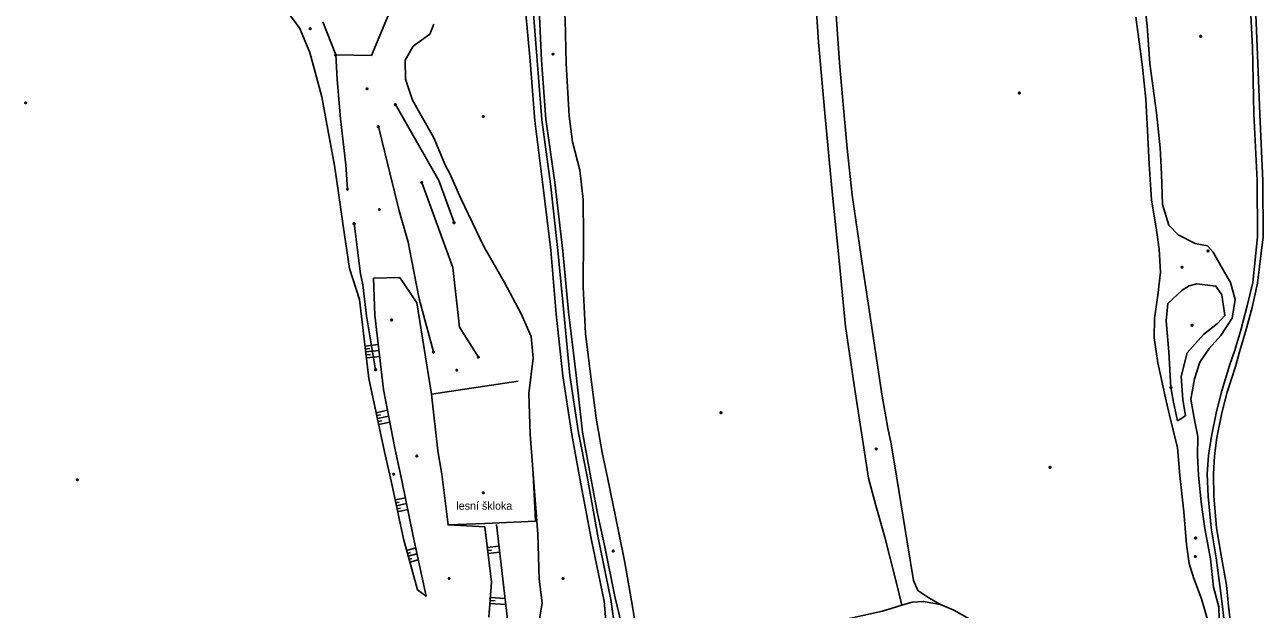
# Model space of a CAD drawing. Extents: x -664960 to -662754, y -993849 to -991145.
# Drawn here: x -663856.5 to -663361.4, y -992059.4 to -991825.9 of the extents above; entities that cross this region are included whole.
import ezdxf

# ---------------------------------------------------------------- set-up
doc = ezdxf.new("R2010")
doc.units = 0
for name, color, linetype in [('Vrstva 13', 7, 'Continuous'), ('Vrstva 18', 7, 'Continuous'), ('Vrstva 27', 7, 'Continuous'), ('Vrstva 28', 7, 'Continuous'), ('Vrstva 33', 7, 'Continuous'), ('Vrstva 63', 7, 'Continuous')]:
    doc.layers.add(name, color=color, linetype=linetype)

msp = doc.modelspace()

# ---------------------------------------------------------------- linework, layer by layer
at = {"layer": 'Vrstva 13'}
for points in [[(-663742.203, -991827.14), (-663742.023, -991827.44), (-663742.203, -991827.74), (-663742.563, -991827.74), (-663742.743, -991827.44), (-663742.563, -991827.14), (-663742.203, -991827.14)], [(-663386.265, -991830.239), (-663386.085, -991830.539), (-663386.265, -991830.839), (-663386.625, -991830.839), (-663386.805, -991830.539), (-663386.625, -991830.239), (-663386.265, -991830.239)], [(-663645.151, -991837.335), (-663644.971, -991837.635), (-663645.151, -991837.935), (-663645.511, -991837.935), (-663645.691, -991837.635), (-663645.511, -991837.335), (-663645.151, -991837.335)], [(-663855.937, -991856.804), (-663855.757, -991857.104), (-663855.937, -991857.404), (-663856.297, -991857.404), (-663856.477, -991857.104), (-663856.297, -991856.804), (-663855.937, -991856.804)], [(-663458.726, -991852.828), (-663458.546, -991853.128), (-663458.726, -991853.428), (-663459.086, -991853.428), (-663459.266, -991853.128), (-663459.086, -991852.828), (-663458.726, -991852.828)], [(-663672.978, -991862.261), (-663672.798, -991862.561), (-663672.978, -991862.861), (-663673.338, -991862.861), (-663673.518, -991862.561), (-663673.338, -991862.261), (-663672.978, -991862.261)], [(-663714.501, -991899.41), (-663714.321, -991899.71), (-663714.501, -991900.01), (-663714.861, -991900.01), (-663715.041, -991899.71), (-663714.861, -991899.41), (-663714.501, -991899.41)], [(-663709.667, -991943.553), (-663709.487, -991943.853), (-663709.667, -991944.153), (-663710.027, -991944.153), (-663710.207, -991943.853), (-663710.027, -991943.553), (-663709.667, -991943.553)], [(-663683.574, -991963.56), (-663683.394, -991963.86), (-663683.574, -991964.16), (-663683.934, -991964.16), (-663684.114, -991963.86), (-663683.934, -991963.56), (-663683.574, -991963.56)], [(-663578.019, -991980.541), (-663577.839, -991980.841), (-663578.019, -991981.141), (-663578.379, -991981.141), (-663578.559, -991980.841), (-663578.379, -991980.541), (-663578.019, -991980.541)], [(-663515.946, -991995.097), (-663515.766, -991995.397), (-663515.946, -991995.697), (-663516.306, -991995.697), (-663516.486, -991995.397), (-663516.306, -991995.097), (-663515.946, -991995.097)], [(-663699.577, -991997.862), (-663699.397, -991998.162), (-663699.577, -991998.462), (-663699.937, -991998.462), (-663700.117, -991998.162), (-663699.937, -991997.862), (-663699.577, -991997.862)], [(-663708.815, -992005.117), (-663708.635, -992005.417), (-663708.815, -992005.717), (-663709.175, -992005.717), (-663709.355, -992005.417), (-663709.175, -992005.117), (-663708.815, -992005.117)], [(-663446.486, -992002.419), (-663446.306, -992002.719), (-663446.486, -992003.019), (-663446.846, -992003.019), (-663447.026, -992002.719), (-663446.846, -992002.419), (-663446.486, -992002.419)], [(-663835.271, -992007.409), (-663835.091, -992007.709), (-663835.271, -992008.009), (-663835.631, -992008.009), (-663835.811, -992007.709), (-663835.631, -992007.409), (-663835.271, -992007.409)], [(-663673.009, -992012.569), (-663672.829, -992012.869), (-663673.009, -992013.169), (-663673.369, -992013.169), (-663673.549, -992012.869), (-663673.369, -992012.569), (-663673.009, -992012.569)], [(-663621.092, -992035.796), (-663620.912, -992036.096), (-663621.092, -992036.396), (-663621.452, -992036.396), (-663621.632, -992036.096), (-663621.452, -992035.796), (-663621.092, -992035.796)], [(-663686.641, -992046.834), (-663686.461, -992047.134), (-663686.641, -992047.434), (-663687.001, -992047.434), (-663687.181, -992047.134), (-663687.001, -992046.834), (-663686.641, -992046.834)], [(-663641.134, -992046.834), (-663640.954, -992047.134), (-663641.134, -992047.434), (-663641.494, -992047.434), (-663641.674, -992047.134), (-663641.494, -992046.834), (-663641.134, -992046.834)]]:
    msp.add_lwpolyline(points, dxfattribs=at)
at = {"layer": 'Vrstva 18'}
msp.add_lwpolyline([(-663398.146, -991970.499), (-663397.966, -991970.799), (-663398.146, -991971.099), (-663398.506, -991971.099), (-663398.686, -991970.799), (-663398.506, -991970.499), (-663398.146, -991970.499)], dxfattribs=at)
at = {"layer": 'Vrstva 27'}
for points in [[(-663361.412, -991910.643), (-663361.623, -991888.2), (-663362.818, -991861.554), (-663363.863, -991834.538), (-663364.841, -991809.195), (-663366.195, -991778.792), (-663366.957, -991752.07), (-663367.559, -991734.45), (-663368.487, -991718.674), (-663370.521, -991706.328), (-663373.676, -991693.914), (-663376.846, -991682.816), (-663380.136, -991671.455)], [(-663652.149, -992072.457), (-663638.894, -992079.322), (-663629.252, -992082.973), (-663622.572, -992083.804), (-663623.507, -992071.963), (-663624.89, -992056.198), (-663630.063, -992031.166), (-663634.545, -992007.215), (-663637.859, -991989.522), (-663641.354, -991966.119), (-663644.017, -991941.494), (-663646.236, -991915.956), (-663649.418, -991889.892), (-663652.546, -991864.285), (-663654.41, -991840.241), (-663656.328, -991820.074), (-663658.665, -991801.934), (-663661.329, -991790.355), (-663663.806, -991781.544)], [(-663660.976, -991780.777), (-663658.558, -991789.771), (-663655.323, -991801.705), (-663653.202, -991819.768), (-663651.587, -991840.172), (-663649.787, -991863.83), (-663646.312, -991889.394), (-663643.411, -991916.091), (-663641.041, -991940.893), (-663638.598, -991965.955), (-663635.066, -991988.904), (-663631.676, -992006.332), (-663627.229, -992030.816), (-663622.18, -992055.438), (-663619.865, -992072.617), (-663618.624, -992084.162), (-663617.662, -992084.005)], [(-663377.22, -992063.049), (-663377.699, -992058.284), (-663378.784, -992049.914), (-663380.202, -992038.9), (-663382.251, -992026.857), (-663383.482, -992014.37), (-663383.821, -992005.315), (-663383.227, -991997.968), (-663382.113, -991990.224), (-663380.112, -991980.382), (-663377.96, -991972.186), (-663374.89, -991962.071), (-663372.759, -991955.93), (-663370.405, -991947.869), (-663367.822, -991938.125), (-663365.571, -991928.886), (-663363.643, -991910.588), (-663363.884, -991888.154), (-663365.195, -991861.515), (-663365.766, -991834.788), (-663367.061, -991809.084)], [(-663368.827, -992107.791), (-663370.164, -992098.616), (-663372.363, -992086.327), (-663373.998, -992073.035), (-663374.823, -992062.726), (-663375.234, -992058.128), (-663376.145, -992049.756), (-663378.119, -992038.642), (-663380.074, -992026.835), (-663381.216, -992014.265), (-663381.345, -992005.43), (-663380.935, -991998.116), (-663379.992, -991990.81), (-663378, -991980.891), (-663375.788, -991972.705), (-663372.407, -991962.063), (-663370.939, -991956.548), (-663368.446, -991948.503), (-663365.781, -991938.856), (-663363.658, -991929.166), (-663361.412, -991910.643)], [(-663610.509, -992083.791), (-663604.798, -992083.037), (-663588.741, -992078.775), (-663568.158, -992073.414), (-663540.034, -992066.054), (-663529.382, -992063.582), (-663513.636, -992060.192), (-663505.874, -992057.816)], [(-663505.874, -992057.816), (-663501.741, -992056.574), (-663497.34, -992056.267), (-663490.468, -992057.436), (-663485.138, -992059.768), (-663476.877, -992064.439), (-663466.765, -992070.371), (-663454.437, -992078.707), (-663436.313, -992089.167), (-663416.04, -992100.061), (-663402.598, -992105.966), (-663390.777, -992109.645), (-663381.893, -992111.637), (-663376.011, -992112.573), (-663374.014, -992111.876)]]:
    msp.add_lwpolyline(points, dxfattribs=at)
at = {"layer": 'Vrstva 28'}
msp.add_line((-663667.952, -992025.484), (-663663.513, -992063.524), dxfattribs=at)
msp.add_lwpolyline([(-663383.345, -991915.977), (-663383.165, -991916.277), (-663383.345, -991916.577), (-663383.705, -991916.577), (-663383.885, -991916.277), (-663383.705, -991915.977), (-663383.345, -991915.977)], dxfattribs=at)
at = {"layer": 'Vrstva 33'}
for points in [[(-663393.659, -991922.432), (-663393.479, -991922.732), (-663393.659, -991923.032), (-663394.019, -991923.032), (-663394.199, -991922.732), (-663394.019, -991922.432), (-663393.659, -991922.432)], [(-663389.677, -991945.654), (-663389.497, -991945.954), (-663389.677, -991946.254), (-663390.037, -991946.254), (-663390.217, -991945.954), (-663390.037, -991945.654), (-663389.677, -991945.654)], [(-663388.28, -992030.609), (-663388.1, -992030.909), (-663388.28, -992031.209), (-663388.64, -992031.209), (-663388.82, -992030.909), (-663388.64, -992030.609), (-663388.28, -992030.609)]]:
    msp.add_lwpolyline(points, dxfattribs=at)
at = {"layer": 'Vrstva 63'}
for p, q in [((-663722.654, -991935.673), (-663718.977, -991967.248)), ((-663720.492, -991954.235), (-663715.156, -991953.614)), ((-663720.354, -991955.427), (-663718.576, -991955.22)), ((-663720.215, -991956.619), (-663714.873, -991955.997)), ((-663720.076, -991957.811), (-663718.296, -991957.604)), ((-663719.937, -991959.003), (-663714.59, -991958.38)), ((-663693.844, -991973.427), (-663659.297, -991968.307)), ((-663693.844, -991973.427), (-663659.297, -991968.307)), ((-663716.037, -991980.864), (-663711.43, -991979.87)), ((-663715.784, -991982.037), (-663714.259, -991981.708)), ((-663715.531, -991983.21), (-663710.978, -991982.227)), ((-663715.278, -991984.383), (-663713.771, -991984.058)), ((-663715.025, -991985.556), (-663710.526, -991984.585)), ((-663708.418, -992015.722), (-663704.321, -992014.854)), ((-663708.169, -992016.896), (-663706.809, -992016.608)), ((-663707.92, -992018.07), (-663703.848, -992017.207)), ((-663707.671, -992019.244), (-663706.319, -992018.957)), ((-663707.422, -992020.418), (-663703.374, -992019.56)), ((-663703.818, -992035.923), (-663700.214, -992034.913)), ((-663671.593, -992034.779), (-663666.935, -992034.201)), ((-663671.446, -992035.97), (-663669.897, -992035.778)), ((-663703.494, -992037.078), (-663702.317, -992036.748)), ((-663703.171, -992038.234), (-663699.706, -992037.263)), ((-663702.847, -992039.389), (-663701.717, -992039.073)), ((-663702.524, -992040.545), (-663699.198, -992039.613)), ((-663671.298, -992037.161), (-663666.657, -992036.585)), ((-663670.326, -992054.644), (-663664.498, -992055.08)), ((-663670.505, -992057.037), (-663664.215, -992057.508)), ((-663670.415, -992055.841), (-663668.398, -992055.992))]:
    msp.add_line(p, q, dxfattribs=at)
for points in [[(-663830.408, -991644.763), (-663822.618, -991651.287), (-663820.006, -991652.738), (-663813.768, -991662.143), (-663806.106, -991678.752), (-663801.417, -991691.012), (-663797.605, -991704.846), (-663793.552, -991718.768), (-663785.857, -991739.61), (-663776.987, -991767.385), (-663773.049, -991783.599), (-663767.674, -991795.713), (-663761.051, -991806.613), (-663756.782, -991813.59), (-663746.666, -991827.078), (-663742.555, -991836.967), (-663737.674, -991854.687), (-663736.023, -991864.162), (-663732.643, -991882.12), (-663731.024, -991893.087), (-663729.22, -991906.236), (-663726.686, -991923.293), (-663722.654, -991935.673)], [(-663544.069, -991664.786), (-663542.145, -991665.697), (-663536.462, -991683.502), (-663535.712, -991698.318), (-663534.725, -991710.824), (-663534.775, -991722.492), (-663535.558, -991731.788), (-663535.259, -991754.11), (-663533.805, -991774.681), (-663533.296, -991796.178), (-663532.455, -991818.084), (-663530.797, -991841.119), (-663529.041, -991860.69), (-663527.667, -991875.317), (-663525.706, -991893.964), (-663521.207, -991924.894), (-663518.409, -991943.227), (-663513.935, -991973.474), (-663511.498, -991987.024)], [(-663519.147, -992007.037), (-663524.931, -991969.808), (-663528.367, -991946.369), (-663530.939, -991920.02), (-663533.573, -991893.927), (-663536.69, -991861.244), (-663539.224, -991832.857), (-663541.068, -991804.157), (-663544.559, -991774.471), (-663545.028, -991753.079), (-663545.015, -991730.228), (-663543.344, -991700.26), (-663552.681, -991698.483), (-663565.859, -991695.74), (-663578.557, -991695.146), (-663592.996, -991693.333), (-663601.144, -991693.417), (-663605.438, -991698.732), (-663611.051, -991709.356), (-663617.609, -991720.889), (-663621.48, -991723.737), (-663630.201, -991722.923), (-663640.545, -991720.884), (-663653.311, -991721.311)], [(-663617.662, -992084.005), (-663617.796, -992070.405), (-663618.685, -992062.035), (-663620.6, -992054.289), (-663624.555, -992034.438), (-663627.573, -992021.077), (-663630.439, -992005.417), (-663633.594, -991988.6), (-663636.017, -991965.823), (-663639.158, -991940.551), (-663641.433, -991916.279), (-663644.548, -991888.909), (-663648.221, -991863.623), (-663649.938, -991840.103), (-663650.821, -991819.63), (-663650.995, -991810.793), (-663652.021, -991800.876), (-663653.776, -991788.518), (-663656.114, -991774.485), (-663657.935, -991762.249), (-663658.157, -991746.16), (-663659.154, -991720.205)], [(-663625.612, -991996.822), (-663628.083, -991983.066), (-663630.213, -991966.493), (-663632.388, -991949.185), (-663633.288, -991930.636), (-663633.176, -991910.364), (-663633.262, -991895.715), (-663634.553, -991883.925), (-663637.482, -991872.717), (-663638.916, -991862.418), (-663640.047, -991841.399), (-663640.409, -991823.803), (-663641.52, -991809.389), (-663642.527, -991800.158), (-663643.533, -991792.531), (-663644.831, -991783.57), (-663648.588, -991764.05), (-663652.178, -991746.436), (-663654.862, -991729.013)], [(-663409.93, -991808.068), (-663407.784, -991826.362), (-663406.711, -991841.386), (-663404.136, -991861.075), (-663402.654, -991875.03), (-663402.096, -991885.411), (-663401.632, -991897.632), (-663399.084, -991906.012), (-663395.377, -991909.831), (-663388.622, -991913.315), (-663383.75, -991914.154), (-663381.381, -991916.777), (-663378.359, -991922.18), (-663374.448, -991928.851), (-663372.696, -991935.607), (-663373.84, -991943.085), (-663378.415, -991950.059), (-663382.995, -991955.275), (-663386.769, -991960.718), (-663388.946, -991967.327), (-663390.339, -991975.505), (-663389.016, -991982.998), (-663387.547, -991990.399), (-663387.697, -991998.065), (-663387.247, -992005.829), (-663386.246, -992016.604), (-663384.703, -992027.163), (-663382.538, -992039.301), (-663381.319, -992050.565), (-663379.225, -992058.386), (-663378.976, -992063.156)], [(-663737.283, -991824.672), (-663732.19, -991837.962), (-663717.901, -991838.173), (-663706.364, -991810.665)], [(-663383.395, -992064.436), (-663386.147, -992055.283), (-663389.182, -992047.166), (-663391.014, -992041.149), (-663392.12, -992033.511), (-663393.132, -992020.521), (-663394.792, -992005.994), (-663395.638, -991994.861), (-663398.839, -991981.862), (-663400.188, -991976.125), (-663403.58, -991960.918), (-663405.06, -991950.913), (-663404.942, -991943.266), (-663403.594, -991933.887), (-663402.508, -991924.699), (-663402.947, -991915.521), (-663404.132, -991907.935), (-663406.109, -991895.822), (-663406.998, -991881.534), (-663407.694, -991868.106), (-663408.337, -991855.618), (-663409.669, -991842.886), (-663410.58, -991835.673), (-663412.273, -991822.802)], [(-663692.989, -991825.647), (-663694.588, -991829.662), (-663701.208, -991834.461), (-663704.472, -991840.084), (-663704.3, -991847.623), (-663701.439, -991856.026), (-663692.974, -991871.045), (-663688.163, -991882.485), (-663686.736, -991885.091), (-663682.167, -991895.332), (-663672.891, -991914.79), (-663664.753, -991928.902), (-663658.017, -991941.425), (-663654.088, -991950.464), (-663653.272, -991959.033), (-663654.919, -991973.174), (-663654.393, -991989.459), (-663653.206, -992005.264), (-663651.407, -992029.332), (-663650.796, -992047.328), (-663649.704, -992056.772), (-663652.149, -992072.457)], [(-663732.01, -991837.662), (-663731.83, -991837.962), (-663732.01, -991838.262), (-663732.37, -991838.262), (-663732.55, -991837.962), (-663732.37, -991837.662), (-663732.01, -991837.662)], [(-663732.19, -991837.962), (-663731.546, -991847.778), (-663730.299, -991863.452), (-663728.178, -991881.811), (-663727.471, -991891.59)], [(-663719.476, -991851.198), (-663719.296, -991851.498), (-663719.476, -991851.798), (-663719.836, -991851.798), (-663720.016, -991851.498), (-663719.836, -991851.198), (-663719.476, -991851.198)], [(-663708.128, -991857.457), (-663707.948, -991857.757), (-663708.128, -991858.057), (-663708.488, -991858.057), (-663708.668, -991857.757), (-663708.488, -991857.457), (-663708.128, -991857.457)], [(-663708.308, -991857.757), (-663690.97, -991888.164), (-663684.882, -991904.936)], [(-663714.958, -991866.282), (-663714.778, -991866.582), (-663714.958, -991866.882), (-663715.318, -991866.882), (-663715.498, -991866.582), (-663715.318, -991866.282), (-663714.958, -991866.282)], [(-663693.101, -991956.608), (-663698.831, -991935.39), (-663701.828, -991919.65), (-663703.274, -991912.775), (-663706.754, -991900.239), (-663712.427, -991877.402), (-663715.138, -991866.582)], [(-663727.291, -991891.29), (-663727.111, -991891.59), (-663727.291, -991891.89), (-663727.651, -991891.89), (-663727.831, -991891.59), (-663727.651, -991891.29), (-663727.291, -991891.29)], [(-663697.627, -991888.627), (-663697.447, -991888.927), (-663697.627, -991889.227), (-663697.987, -991889.227), (-663698.167, -991888.927), (-663697.987, -991888.627), (-663697.627, -991888.627)], [(-663697.807, -991888.927), (-663685.399, -991922.871), (-663682.693, -991946.723), (-663675.162, -991958.695)], [(-663724.649, -991905.043), (-663724.469, -991905.343), (-663724.649, -991905.643), (-663725.009, -991905.643), (-663725.189, -991905.343), (-663725.009, -991905.043), (-663724.649, -991905.043)], [(-663724.829, -991905.343), (-663722.321, -991925.427), (-663721.281, -991929.725), (-663719.839, -991942.238), (-663716.239, -991963.697)], [(-663684.702, -991904.636), (-663684.522, -991904.936), (-663684.702, -991905.236), (-663685.062, -991905.236), (-663685.242, -991904.936), (-663685.062, -991904.636), (-663684.702, -991904.636)], [(-663716.554, -991941.844), (-663717.053, -991927.15), (-663706.587, -991926.906), (-663699.749, -991936.967)], [(-663395.723, -991984.06), (-663392.487, -991982.062), (-663393.587, -991975.585), (-663394.241, -991966.445), (-663391.792, -991957.003), (-663385.338, -991949.624), (-663379.71, -991945.253), (-663376.702, -991942.103), (-663378.013, -991933.796), (-663380.338, -991930.279), (-663387.959, -991929.367), (-663391.051, -991930.218), (-663393.796, -991931.983), (-663399.494, -991937.241), (-663400.163, -991944.119), (-663399.206, -991956.608), (-663398.326, -991970.799), (-663397.295, -991976.682), (-663395.723, -991984.06)], [(-663699.749, -991936.967), (-663693.844, -991973.427), (-663691.355, -991996.113), (-663689.796, -992005.488), (-663687.235, -992025.666), (-663672.569, -992025.158), (-663652.279, -992024.158), (-663653.206, -992005.264)], [(-663718.977, -991967.248), (-663712.675, -991996.439), (-663709.885, -992008.803), (-663705.12, -992031.274), (-663699.436, -992051.571), (-663696.06, -992054.137), (-663701.245, -992030.14), (-663705.705, -992007.975), (-663708.511, -991995.095), (-663713.027, -991971.538), (-663716.554, -991941.844)], [(-663692.921, -991956.308), (-663692.741, -991956.608), (-663692.921, -991956.908), (-663693.281, -991956.908), (-663693.461, -991956.608), (-663693.281, -991956.308), (-663692.921, -991956.308)], [(-663674.982, -991958.395), (-663674.802, -991958.695), (-663674.982, -991958.995), (-663675.342, -991958.995), (-663675.522, -991958.695), (-663675.342, -991958.395), (-663674.982, -991958.395)], [(-663716.059, -991963.397), (-663715.879, -991963.697), (-663716.059, -991963.997), (-663716.419, -991963.997), (-663716.599, -991963.697), (-663716.419, -991963.397), (-663716.059, -991963.397)], [(-663511.498, -991987.024), (-663510.193, -991993.33), (-663507.826, -992007.034), (-663503.802, -992032.442), (-663501.223, -992047.94), (-663499.492, -992051.953), (-663495.118, -992054.791), (-663490.468, -992057.436)], [(-663625.612, -991996.822), (-663623.58, -992006.69), (-663618.949, -992028.863), (-663616.597, -992040.728), (-663613.419, -992059.024), (-663611.042, -992074.3), (-663610.509, -992083.791)], [(-663519.147, -992007.037), (-663516.23, -992017.996), (-663512.704, -992030.615), (-663507.961, -992049.002), (-663505.874, -992057.816)], [(-663687.235, -992025.666), (-663672.631, -992026.425), (-663669.875, -992048.621), (-663670.915, -992062.515)], [(-663388.342, -992037.982), (-663388.162, -992038.282), (-663388.342, -992038.582), (-663388.702, -992038.582), (-663388.882, -992038.282), (-663388.702, -992037.982), (-663388.342, -992037.982)]]:
    msp.add_lwpolyline(points, dxfattribs=at)

# ---------------------------------------------------------------- texts
msp.add_text('lesní škloka', height=3.2, dxfattribs=at).set_placement((-663683.947, -992019.63))

doc.saveas('drawing.dxf')
